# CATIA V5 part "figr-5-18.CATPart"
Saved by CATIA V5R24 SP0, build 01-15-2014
Part number: Part1
Bounding box of the stored display mesh (mm): x -50 to 50, y -70 to 70, z -20 to 40
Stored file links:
  D:\KAVITA\CATIA V5-6R2014 Project_ Kavita\CATIA V5-6R2014_partfiles\Partfiles\c05_catia_v5-6r2014_prt\figr-5-18.CATPart
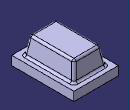
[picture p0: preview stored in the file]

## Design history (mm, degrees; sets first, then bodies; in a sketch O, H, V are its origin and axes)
Body1 (main body)
  Sketch1 on xy-plane, origin (0, 0, 0), H (1, 0, 0), V (0, 1, 0)
    line L1 (50, 70) -> (50, -70)
    line L2 (50, -70) -> (-50, -70)
    line L3 (-50, -70) -> (-50, 70)
    line L4 (-50, 70) -> (50, 70)
    length L2 = 100
    length L1 = 140
    vertical: L1 V, L3 V
    horizontal: L2 H, L4 H
    equidistance: L1 L3 O, L2 L4 O
  Pad1: profile Sketch1, direction (0, 0, -1), length 20
  Sketch2 on face of Pad1, origin (0, 0, 0), H (1, 0, 0), V (0, 1, 0)
    line L1 (30, 50) -> (30, -50)
    line L2 (30, -50) -> (-30, -50)
    line L3 (-30, -50) -> (-30, 50)
    line L4 (-30, 50) -> (30, 50)
    length L2 = 60
    length L1 = 100
    vertical: L1 V, L3 V
    horizontal: L2 H, L4 H
    equidistance: L1 L3 O, L2 L4 O
  Pad2: profile Sketch2, direction (0, 0, 1), length 40, opposite side up to face of Pad1
  Draft1: Angle 9, Neutral face of Pad2, PullDir face of Pad2, SupportToDraft (face of Pad2; face of Pad2; face of Pad2; face of Pad2)
  Fillet1: radius 5, on edge [face of Pad2 | face of Pad2] (x4)
  Fillet2: radius 5, on edge [face of Pad2 | face of Pad2] (x4)
  Fillet3: radius 5, on edge [face of Pad2 | face of Pad1] (x4)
